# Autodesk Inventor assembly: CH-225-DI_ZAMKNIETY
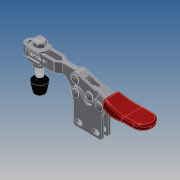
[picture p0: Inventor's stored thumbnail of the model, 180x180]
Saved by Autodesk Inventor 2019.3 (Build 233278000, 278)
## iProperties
Company: Î¢ÈíÖÐ¹ú
Created: 2013-01
Part Number: CH-225-DI_ZAMKNIETY
Material: Ogólny
Description: STEP AP203
Document SubType Name: Assembly
Designer: CADENGINEERING4
Sending System: SolidWorks 2010
Preprocessor: SwSTEP 2.0
Title: CH-225-DI.STEP
Author: Î¢ÈíÓÃ»§
Revision Number: ÈÎºÎ
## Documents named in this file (9)
- E:\STRONA\Horizontal toggle clamp\CH-225-DI\CH-225-DI_ZAMKNIETY.iam
- E:\STRONA\Horizontal toggle clamp\CH-225-DI\225-DI-02.ipt
- E:\STRONA\Horizontal toggle clamp\CH-225-DI\225-D-04___.ipt
- E:\STRONA\Horizontal toggle clamp\CH-225-DI\56212-01___.ipt
- E:\STRONA\Horizontal toggle clamp\CH-225-DI\225-D-05___.ipt
- E:\STRONA\Horizontal toggle clamp\CH-225-DI\FW-516___.ipt
- E:\STRONA\Horizontal toggle clamp\CH-225-DI\225-DI-01___.ipt
- E:\STRONA\Horizontal toggle clamp\CH-225-DI\225-D-03___.iam
- E:\STRONA\Horizontal toggle clamp\CH-225-DI\CH-FC-56212___.ipt
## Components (14 placed, 14 different names)
1. 225-DI-02_1 — Równoległe:1, Zestawiające:7, Zestawiające:8, Zestawiające:9, Zestawiające:21, Zestawiające:22, Zestawiające:25
2. 225-D-04____2 — Zestawiające:10, Zestawiające:11, Zestawiające:12, Zestawiające:15, Zestawiające:16
3. 56212-01____3 — Zestawiające:2, Zestawiające:5
4. 225-D-05____4 — Zestawiające:23, Zestawiające:24
5. 225-D-04____5 — Zestawiające:10, Zestawiające:11, Zestawiające:12, Zestawiające:13, Zestawiające:14
6. 225-D-05____6 — Zestawiające:26, Zestawiające:27
7. FW-516____7 — Równoległe:2, Zestawiające:4, Zestawiające:5, Zestawiające:7
8. FW-516____8 — Równoległe:1, Równoległe:2, Zestawiające:3, Zestawiające:6, Zestawiające:8
9. 225-DI-01____9 — Zestawiające:13, Zestawiające:14, Zestawiające:19, Zestawiające:20, Zestawiające:21, Zestawiające:22, Zestawiające:23, Zestawiające:24, Przejściowe:1
10. 225-D-05____10 — Zestawiające:15, Zestawiające:17, Zestawiające:18
11. 225-D-03____11 [sub-assembly] — Zestawiające:16, Zestawiające:17, Zestawiające:18, Zestawiające:25, Zestawiające:26, Zestawiające:27, Przejściowe:1
12. 56212-01____12 — Równoległe:3, Zestawiające:1, Zestawiające:6
13. 225-D-05____13 — Zestawiające:19, Zestawiające:20
14. CH-FC-56212____14 — Równoległe:3, Zestawiające:1, Zestawiające:2, Zestawiające:3, Zestawiające:4, Zestawiające:9
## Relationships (31: Mate 27, Flush 3, Transitional 1)
- Równoległe:1 [Flush]: 225-DI-02_1 ↔ FW-516____8
- Równoległe:2 [Flush]: FW-516____7 ↔ FW-516____8
- Równoległe:3 [Flush]: 56212-01____12 ↔ CH-FC-56212____14
- Zestawiające:1 [Mate]: 56212-01____12 ↔ CH-FC-56212____14
- Zestawiające:2 [Mate]: 56212-01____3 ↔ CH-FC-56212____14
- Zestawiające:3 [Mate]: FW-516____8 ↔ CH-FC-56212____14
- Zestawiające:4 [Mate]: FW-516____7 ↔ CH-FC-56212____14
- Zestawiające:5 [Mate]: 56212-01____3 ↔ FW-516____7
- Zestawiające:6 [Mate]: FW-516____8 ↔ 56212-01____12
- Zestawiające:7 [Mate]: 225-DI-02_1 ↔ FW-516____7
- Zestawiające:8 [Mate]: 225-DI-02_1 ↔ FW-516____8
- Zestawiające:9 [Mate]: 225-DI-02_1 ↔ CH-FC-56212____14
- Zestawiające:10 [Mate]: 225-D-04____2 ↔ 225-D-04____5
- Zestawiające:11 [Mate]: 225-D-04____2 ↔ 225-D-04____5
- Zestawiające:12 [Mate]: 225-D-04____2 ↔ 225-D-04____5
- Zestawiające:13 [Mate]: 225-D-04____5 ↔ 225-DI-01____9
- Zestawiające:14 [Mate]: 225-D-04____5 ↔ 225-DI-01____9
- Zestawiające:15 [Mate]: 225-D-04____2 ↔ 225-D-05____10
- Zestawiające:16 [Mate]: 225-D-04____2 ↔ 225-D-03____11
- Zestawiające:17 [Mate]: 225-D-05____10 ↔ 225-D-03____11
- Zestawiające:18 [Mate]: 225-D-05____10 ↔ 225-D-03____11
- Zestawiające:19 [Mate]: 225-DI-01____9 ↔ 225-D-05____13
- Zestawiające:20 [Mate]: 225-DI-01____9 ↔ 225-D-05____13
- Zestawiające:21 [Mate]: 225-DI-02_1 ↔ 225-DI-01____9
- Zestawiające:22 [Mate]: 225-DI-02_1 ↔ 225-DI-01____9
- Zestawiające:23 [Mate]: 225-D-05____4 ↔ 225-DI-01____9
- Zestawiające:24 [Mate]: 225-D-05____4 ↔ 225-DI-01____9
- Zestawiające:25 [Mate]: 225-DI-02_1 ↔ 225-D-03____11
- Zestawiające:26 [Mate]: 225-D-05____6 ↔ 225-D-03____11
- Zestawiające:27 [Mate]: 225-D-05____6 ↔ 225-D-03____11
- Przejściowe:1 [Transitional]: 225-DI-01____9 ↔ 225-D-03____11
